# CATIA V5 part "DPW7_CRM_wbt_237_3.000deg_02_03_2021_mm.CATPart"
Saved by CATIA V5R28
Part number: DPW7_CRM_wbt_237_2.995deg_02_03_2021
Bounding box of the stored display mesh (mm): x 2349.5 to 66711.891, y 0 to 29520.396, z 2310.119 to 8715.756
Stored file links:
  Z:\Scratch\04_CAD_Allgemein\Flight2Jig\Output\DPW-7\CATPart\DPW7_CRM_wbt_237_2.995deg_02_03_2021.CATPart
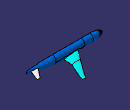
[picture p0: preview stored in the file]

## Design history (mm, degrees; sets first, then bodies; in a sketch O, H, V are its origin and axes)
Set1
  DatumSurface1 "Clean_Wing"
  DatumSurface2 "Fuselage"
  DatumSurface3 "HTP"
  DatumSurface4 "Symmetry"
  DatumSurface5 "Farfield"
Body1 (main body)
